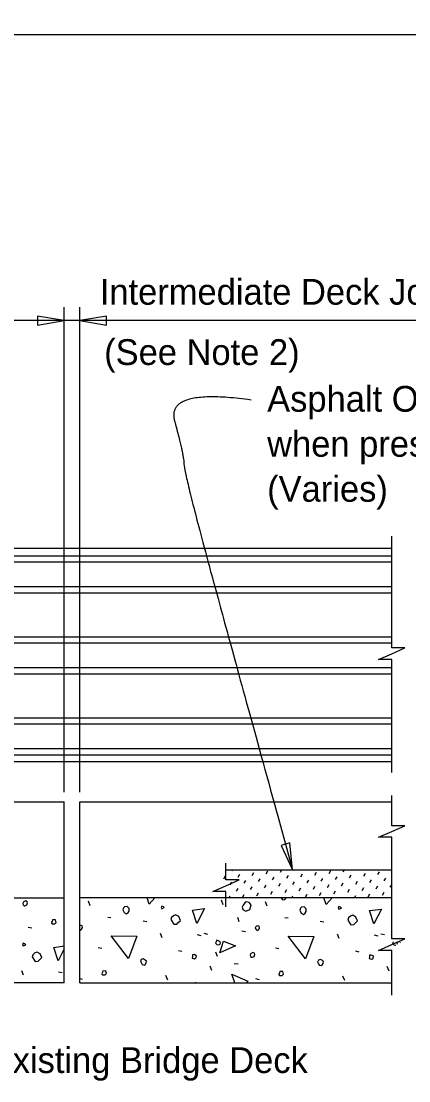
# Model space of a CAD drawing. Extents: x 0 to 41.1, y 0 to 25.9.
# Drawn here: x 12.62 to 15.65, y 4.79 to 13.07 of the extents above; entities that cross this region are included whole.
import ezdxf

# ---------------------------------------------------------------- set-up
doc = ezdxf.new("R2010")
doc.units = 0
for name, color, linetype in [('Dimension', 7, 'Continuous'), ('ExistSuperStruct', 7, 'Continuous'), ('Miscellaneous', 7, 'Continuous'), ('SteelMisc', 7, 'Continuous'), ('TextStructures', 7, 'Continuous')]:
    doc.layers.add(name, color=color, linetype=linetype)

msp = doc.modelspace()

# ---------------------------------------------------------------- linework, layer by layer
at = {"layer": 'Dimension'}
for p, q in [((12.9587, 7.046), (12.9587, 10.8371)), ((13.0812, 7.046), (13.0812, 10.8371)), ((16.9838, 10.7322), (11.4323, 10.7322))]:
    msp.add_line(p, q, dxfattribs=at)
for points in [[(5.0851, 12.9697), (11.2162, 12.9697), (11.2162, 13.0731), (11.2612, 12.9697), (11.3062, 12.8664), (11.3062, 12.9697), (17.272, 12.9697)], [(15.5194, 7.1992), (15.5194, 8.0824), (15.4161, 8.0824), (15.5194, 8.1274), (15.6227, 8.1724), (15.5194, 8.1724), (15.5194, 9.0453)], [(15.5194, 6.2223), (15.5194, 6.6924), (15.4161, 6.6924), (15.5194, 6.7374), (15.6227, 6.7824), (15.5194, 6.7824), (15.5194, 7.0198)], [(14.2228, 6.1477), (14.2228, 6.2686), (14.1195, 6.2686), (14.2228, 6.3136), (14.3261, 6.3586), (14.2228, 6.3586), (14.2228, 6.4892)], [(15.5194, 5.4572), (15.5194, 5.8078), (15.4161, 5.8078), (15.5194, 5.8528), (15.6227, 5.8978), (15.5194, 5.8978), (15.5194, 6.2223)]]:
    msp.add_lwpolyline(points, dxfattribs=at)
for points in [[(12.9586, 10.7322), (12.7504, 10.7675), (12.7504, 10.6969)], [(13.0811, 10.7322), (13.2894, 10.6969), (13.2894, 10.7675)], [(14.7446, 6.4374), (14.7231, 6.6476), (14.6551, 6.6288)]]:
    msp.add_lwpolyline(points, close=True, dxfattribs=at)
msp.add_open_spline([(14.4194, 10.1107), (13.7513, 10.2043), (13.8916, 9.6894), (13.8964, 9.5486), (14.172, 8.5092), (14.7445, 6.4374)], degree=2, dxfattribs=at)
at = {"layer": 'ExistSuperStruct'}
for p, q in [((7.379, 6.9697), (12.9587, 6.9697)), ((12.9587, 5.553), (12.9587, 6.9697)), ((13.0812, 5.553), (13.0812, 6.9697)), ((13.0812, 6.9697), (15.5194, 6.9697)), ((14.2228, 6.4386), (15.5194, 6.4386)), ((7.379, 6.2197), (12.9587, 6.2197)), ((15.5194, 6.2197), (13.0812, 6.2197)), ((12.9587, 5.553), (7.379, 5.553)), ((13.0812, 5.553), (15.5194, 5.553))]:
    msp.add_line(p, q, dxfattribs=at)
at = {"layer": 'Miscellaneous'}
for p, q in [((14.2068, 6.3682), (14.2198, 6.3906)), ((14.2686, 6.43), (14.2736, 6.4386)), ((14.3174, 6.3811), (14.3304, 6.4035)), ((14.4281, 6.3941), (14.441, 6.4165)), ((14.5387, 6.4071), (14.5517, 6.4294)), ((14.5875, 6.3582), (14.6005, 6.3806)), ((14.6493, 6.42), (14.6601, 6.4386)), ((14.6982, 6.3712), (14.7111, 6.3936)), ((14.76, 6.433), (14.7632, 6.4386)), ((14.8088, 6.3841), (14.8218, 6.4065)), ((14.9194, 6.3971), (14.9324, 6.4195)), ((15.0301, 6.4101), (15.043, 6.4325)), ((15.0789, 6.3612), (15.0919, 6.3836)), ((15.1407, 6.423), (15.1497, 6.4386)), ((15.1895, 6.3742), (15.2025, 6.3966)), ((15.2513, 6.436), (15.2528, 6.4386)), ((15.3002, 6.3872), (15.3131, 6.4096)), ((15.4108, 6.4001), (15.4238, 6.4225)), ((14.2556, 6.3193), (14.2686, 6.3417)), ((14.3663, 6.3323), (14.3792, 6.3547)), ((14.4151, 6.2835), (14.4281, 6.3059)), ((14.4769, 6.3453), (14.4899, 6.3677)), ((14.5257, 6.2964), (14.5387, 6.3188)), ((14.6364, 6.3094), (14.6493, 6.3318)), ((14.747, 6.3224), (14.76, 6.3447)), ((14.8576, 6.3353), (14.8706, 6.3577)), ((14.9065, 6.2865), (14.9194, 6.3089)), ((14.9683, 6.3483), (14.9812, 6.3707)), ((15.0171, 6.2994), (15.0301, 6.3218)), ((15.1277, 6.3124), (15.1407, 6.3348)), ((15.2384, 6.3254), (15.2513, 6.3478)), ((15.2872, 6.2765), (15.3002, 6.2989)), ((15.349, 6.3383), (15.362, 6.3607)), ((15.3978, 6.2895), (15.4108, 6.3119)), ((15.4596, 6.3513), (15.4726, 6.3737)), ((15.5085, 6.3025), (15.5194, 6.3214)), ((14.249, 6.2197), (14.2556, 6.2311)), ((14.3045, 6.2705), (14.3174, 6.2929)), ((14.3533, 6.2217), (14.3663, 6.2441)), ((14.4639, 6.2346), (14.4769, 6.257)), ((14.5746, 6.2476), (14.5875, 6.27)), ((14.6355, 6.2197), (14.6364, 6.2211)), ((14.6852, 6.2606), (14.6982, 6.2829)), ((14.7386, 6.2197), (14.747, 6.2341)), ((14.7958, 6.2735), (14.8088, 6.2959)), ((14.8447, 6.2247), (14.8576, 6.2471)), ((14.9553, 6.2376), (14.9683, 6.26)), ((15.0659, 6.2506), (15.0789, 6.273)), ((15.1251, 6.2197), (15.1277, 6.2242)), ((15.1766, 6.2636), (15.1895, 6.286)), ((15.2283, 6.2197), (15.2384, 6.2371)), ((15.336, 6.2277), (15.349, 6.2501)), ((15.4467, 6.2407), (15.4596, 6.2631)), ((13.1614, 6.1565), (13.1473, 6.1919)), ((14.202, 6.1647), (14.1879, 6.2001)), ((14.5461, 6.153), (14.5319, 6.1883)), ((13.2993, 6.0681), (13.324, 6.0646)), ((14.3275, 6.0322), (14.3151, 6.0657)), ((14.684, 6.0646), (14.7087, 6.0611)), ((12.6762, 5.9906), (12.7045, 5.9836)), ((13.5751, 6.0399), (13.6051, 6.0345)), ((14.9597, 6.0363), (14.9898, 6.031)), ((13.7236, 5.9055), (13.7112, 5.9391)), ((13.9976, 5.932), (14.0259, 5.9249)), ((14.05, 5.942), (14.0783, 5.9349)), ((14.3463, 5.9603), (14.3764, 5.955)), ((15.1082, 5.902), (15.0959, 5.9356)), ((15.3822, 5.9285), (15.4105, 5.9214)), ((15.4347, 5.9385), (15.4629, 5.9314)), ((13.2251, 5.8313), (13.2516, 5.826)), ((13.8508, 5.8065), (13.8774, 5.8012)), ((14.6097, 5.8277), (14.6362, 5.8224)), ((15.2355, 5.803), (15.262, 5.7977)), ((14.156, 5.7594), (14.1437, 5.793)), ((12.6397, 5.6147), (12.6273, 5.6483)), ((12.9137, 5.6413), (12.942, 5.6342)), ((14.1136, 5.6498), (14.0995, 5.6852)), ((14.2862, 5.7057), (14.318, 5.7022)), ((15.4983, 5.6463), (15.4841, 5.6816)), ((13.0812, 5.5879), (13.0978, 5.5838)), ((13.7678, 5.5749), (13.7536, 5.6103)), ((14.4542, 5.5873), (14.4825, 5.5802)), ((15.1524, 5.5714), (15.1383, 5.6067))]:
    msp.add_line(p, q, dxfattribs=at)
for points in [[(13.6228, 6.1689), (13.6063, 6.2197)], [(13.6658, 6.2197), (13.6228, 6.1689)], [(14.656, 6.2197), (14.6645, 6.2043), (14.684, 6.206), (14.6928, 6.2184), (14.6929, 6.2197)], [(15.0075, 6.1654), (14.9898, 6.2197)], [(15.0534, 6.2197), (15.0075, 6.1654)], [(12.6444, 6.1568), (12.6514, 6.1568), (12.6656, 6.1639), (12.6709, 6.1798), (12.6691, 6.1886), (12.655, 6.1957), (12.6373, 6.1851), (12.6337, 6.1745), (12.6373, 6.1639), (12.6444, 6.1568)], [(13.416, 6.1247), (13.4266, 6.1035), (13.4443, 6.0929), (13.4584, 6.1035), (13.4655, 6.1141), (13.4655, 6.1353), (13.4496, 6.1512), (13.4301, 6.1495), (13.4213, 6.1406), (13.416, 6.1247)], [(13.7218, 6.1335), (13.7412, 6.1424), (13.7342, 6.1495), (13.7218, 6.1548), (13.7165, 6.1424), (13.7218, 6.1335)], [(13.9952, 6.018), (13.9616, 6.1223), (14.0553, 6.1347), (13.9952, 6.018)], [(14.3558, 6.1276), (14.3788, 6.1152), (14.4088, 6.1276), (14.4212, 6.1647), (14.4035, 6.1824), (14.3805, 6.1877), (14.3699, 6.1806), (14.3576, 6.1612), (14.3487, 6.1453), (14.3558, 6.1276)], [(14.8006, 6.1212), (14.8113, 6.1), (14.8289, 6.0893), (14.8431, 6.1), (14.8501, 6.1106), (14.8501, 6.1318), (14.8342, 6.1477), (14.8148, 6.1459), (14.806, 6.1371), (14.8006, 6.1212)], [(15.1065, 6.13), (15.1259, 6.1388), (15.1188, 6.1459), (15.1065, 6.1512), (15.1012, 6.1388), (15.1065, 6.13)], [(15.3799, 6.0145), (15.3463, 6.1188), (15.44, 6.1312), (15.3799, 6.0145)], [(13.7925, 6.0487), (13.8155, 6.0116), (13.8385, 6.0133), (13.8473, 6.0222), (13.8668, 6.0416), (13.8544, 6.0717), (13.8296, 6.0858), (13.812, 6.0787), (13.7978, 6.0646), (13.7925, 6.0487)], [(15.1772, 6.0452), (15.2002, 6.008), (15.2231, 6.0098), (15.232, 6.0186), (15.2514, 6.0381), (15.2391, 6.0681), (15.2143, 6.0823), (15.1966, 6.0752), (15.1825, 6.0611), (15.1772, 6.0452)], [(12.8636, 6.0154), (12.8848, 6.0154), (12.8954, 6.026), (12.8901, 6.0454), (12.8671, 6.0472), (12.8636, 6.0366), (12.8583, 6.0278), (12.8636, 6.0154), (12.86, 6.0189)], [(13.0812, 5.968), (13.0836, 5.9656), (13.0942, 5.9727), (13.1013, 5.9833), (13.0978, 6.001), (13.0889, 6.0027), (13.0812, 6.0016)], [(14.4577, 5.9727), (14.4683, 5.9621), (14.4789, 5.9691), (14.486, 5.9797), (14.4825, 5.9974), (14.4736, 5.9992), (14.4612, 5.9974), (14.4506, 5.9868), (14.4577, 5.9727)], [(13.4602, 5.7446), (13.3258, 5.9214), (13.5256, 5.9196), (13.4602, 5.7446)], [(14.1525, 5.8536), (14.1649, 5.8518), (14.1773, 5.8571), (14.1808, 5.8678), (14.1755, 5.8766), (14.1649, 5.8837), (14.1525, 5.889), (14.1454, 5.8748), (14.1419, 5.8642), (14.1525, 5.8536)], [(14.8448, 5.7411), (14.7105, 5.9179), (14.9103, 5.9161), (14.8448, 5.7411)], [(12.6379, 5.8428), (12.6574, 5.8516), (12.6503, 5.8587), (12.6379, 5.864), (12.6326, 5.8516), (12.6379, 5.8428)], [(12.9113, 5.7272), (12.8777, 5.8315), (12.9587, 5.8422)], [(12.9587, 5.8193), (12.9113, 5.7272)], [(14.1749, 5.7888), (14.2031, 5.8808), (14.2968, 5.8436), (14.1749, 5.7888)], [(15.5315, 5.8741), (15.5301, 5.8713), (15.5266, 5.8607), (15.5372, 5.8501)], [(15.5372, 5.8501), (15.5496, 5.8483), (15.5514, 5.8491)], [(15.5628, 5.8561), (15.5655, 5.8642), (15.5602, 5.8731), (15.5586, 5.8741)], [(15.5857, 5.8703), (15.5869, 5.8741)], [(12.7086, 5.7579), (12.7316, 5.7208), (12.7546, 5.7226), (12.7634, 5.7314), (12.7829, 5.7509), (12.7705, 5.7809), (12.7457, 5.795), (12.7281, 5.788), (12.7139, 5.7738), (12.7086, 5.7579)], [(13.5592, 5.7128), (13.568, 5.6969), (13.5892, 5.6934), (13.5981, 5.7093), (13.6016, 5.7234), (13.5927, 5.7323), (13.5768, 5.7411), (13.5609, 5.7358), (13.5556, 5.7199), (13.5592, 5.7128)], [(13.9587, 5.7482), (13.9781, 5.7429), (13.9905, 5.7517), (13.9923, 5.7641), (13.9887, 5.7676), (13.9746, 5.7747), (13.9622, 5.7729), (13.9604, 5.7605), (13.9587, 5.7482)], [(14.4223, 5.7535), (14.4294, 5.7535), (14.4436, 5.7605), (14.4489, 5.7765), (14.4471, 5.7853), (14.433, 5.7924), (14.4153, 5.7818), (14.4117, 5.7712), (14.4153, 5.7605), (14.4223, 5.7535)], [(14.9438, 5.7093), (14.9527, 5.6934), (14.9739, 5.6898), (14.9827, 5.7057), (14.9863, 5.7199), (14.9774, 5.7287), (14.9615, 5.7376), (14.9456, 5.7323), (14.9403, 5.7164), (14.9438, 5.7093)], [(15.3434, 5.7446), (15.3628, 5.7393), (15.3752, 5.7482), (15.3769, 5.7605), (15.3734, 5.7641), (15.3593, 5.7712), (15.3469, 5.7694), (15.3451, 5.757), (15.3434, 5.7446)], [(13.2569, 5.6156), (13.2781, 5.6156), (13.2887, 5.6262), (13.2834, 5.6456), (13.2604, 5.6474), (13.2569, 5.6368), (13.2516, 5.628), (13.2569, 5.6156), (13.2533, 5.6191)], [(14.6415, 5.6121), (14.6628, 5.6121), (14.6734, 5.6227), (14.6681, 5.6421), (14.6451, 5.6439), (14.6415, 5.6333), (14.6362, 5.6244), (14.6415, 5.6121), (14.638, 5.6156)], [(13.9894, 5.553), (13.9828, 5.5543), (13.9788, 5.553)], [(14.2915, 5.553), (14.2692, 5.6215), (14.3947, 5.5667), (14.3831, 5.553)]]:
    msp.add_lwpolyline(points, dxfattribs=at)
at = {"layer": 'SteelMisc'}
for p, q in [((15.5194, 8.9488), (7.379, 8.9488)), ((7.379, 8.8933), (15.5194, 8.8933)), ((7.379, 8.8451), (15.5194, 8.8451)), ((7.379, 8.6523), (15.5194, 8.6523)), ((7.379, 8.6041), (15.5194, 8.6041)), ((7.379, 8.2601), (15.5194, 8.2601)), ((7.379, 8.2119), (15.5194, 8.2119)), ((7.379, 8.0191), (15.5194, 8.0191)), ((7.379, 7.9709), (15.5194, 7.9709)), ((7.379, 7.627), (15.5194, 7.627)), ((7.379, 7.5787), (15.5194, 7.5787)), ((7.379, 7.3859), (15.5194, 7.3859)), ((7.379, 7.3377), (15.5194, 7.3377)), ((15.5194, 7.2822), (7.379, 7.2822))]:
    msp.add_line(p, q, dxfattribs=at)

# ---------------------------------------------------------------- texts
at = {"layer": 'Dimension'}
for s, p in [('Asphalt Overlay', (14.5454, 10.0197)), ('when present', (14.5454, 9.6677)), ('(Varies)', (14.5454, 9.3157))]:
    msp.add_text(s, height=0.2016, dxfattribs=at).set_placement(p)
at = {"layer": 'TextStructures'}
for s, p in [('Intermediate Deck Joint', (13.2366, 10.8564)), ('(See Note 2)', (13.2708, 10.385)), ('Existing Bridge Deck', (12.3759, 4.8489))]:
    msp.add_text(s, height=0.2016, dxfattribs=at).set_placement(p)

doc.saveas('drawing.dxf')
